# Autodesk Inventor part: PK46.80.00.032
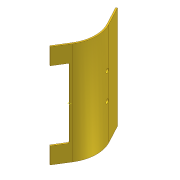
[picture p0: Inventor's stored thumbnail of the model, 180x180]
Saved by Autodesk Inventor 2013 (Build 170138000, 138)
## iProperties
Shininess: 64.0
Length Units: 11269
Angle Units: 11279
Time Units: 11290
Mass Units: 11283
Length Display Precision: 3
Angle Display Precision: 2
Compacted: True
Part Number: PK46.80.00.032
Document SubType Name: Sheet Metal
Created: 2005-01
Material: Steel, Mild
Designer: SAlex
Manufacturer: Standard
Standards Organization: Custom
Density: 7.86 g/cm^3
Flat Pattern Width: 136.565 cm
Flat Pattern Length: 151.087 cm
Flat Pattern Area: 20633.1 cm^2
Sheet Metal Rule: Default
Mass: 119662 g
Surface Area: 19816.5 cm^2
Volume: 15224.2 cm^3
Density: 0.0
Volumn: 0.0
Area: 0.0
PropertySet Name: Model Information
Control State: 0
Master: False
Checked Out: False
Checked Out Date: 2008-10-15
Last Check In Date: 2008-10-15
Author: SAlex
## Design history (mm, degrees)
node "Contour Flange1"
  sketch "Sketch1"
    geometry: L1 (0, 0)-(105.376, 169.988); L2 (118.157, 577.787)-(0, 798.103); A1 r 408 centre (-241.398, 384.956) between (105.376, 169.988) and (118.157, 577.787)
    constraints: 4 end point, 2 point on circle, 2 tangent, 1 centre point, 1 other
    dimensions: "d1" = 60 deg dimension on A1.centre L2.start L1.end; "d2" = 200 distance of L1.start L1.end; "d3" = 408 radius of A1; "d4" = 250 distance of L2.start L2.end; "d5" = 0 horizontal distance of L2.end L1.start
sketch "Sketch2"
  geometry: L1 (1240, -200)-(1240, 0) reference; L2 (0, -200)-(0, 0) reference; L3 (0, -200)-(1240, -200) reference; L4 (200, -200)-(1040, -200); L5 (1040, -200)-(1040, -30); L6 (1040, -30)-(200, -30); L7 (200, -30)-(200, -200)
  constraints: 8 end point, 2 parallel, 1 horizontal, 1 perpendicular, 1 point on line
  dimensions: "d13" = 200 distance between parallel lines of L7 L2; "d14" = 200 distance between parallel lines of L1 L5 (= d13); "d15" = 170 distance between parallel lines of L3 L6
extrude "Extrusion1" cut sketch "Sketch2" stored distance "d16" = 10; taper "d17" = 0 deg
fillet "Fillet1" dims "d18" = 10
workplane "Work Plane1"
sketch "Sketch4"
  geometry: L1 (0, 250)-(0, 0) reference; L2 (1240, 250)-(0, 250) reference; C1 r 25 at (460, -45); C2 r 25 at (780, -45)
  constraints: 2 centre point, 1 equal radius
  dimensions: "d24" = 0 vertical distance of C2.centre C1.centre; "d25" = 295 distance from line of C1.centre L2; "d26" = 50 diameter of C1; "d27" = 320 distance of C2.centre C1.centre; "d28" = 460 distance from line of C1.centre L1
extrude "Extrusion3" cut sketch "Sketch4" stored distance "d29" = 10; taper "d30" = 0 deg
body "Solid1"
face "Plate1" dims "d6" = 1240, "d7" = 16 (= BendReliefWidth), "d9" = 32 (= MinimumRemnant), "d11" = 16 (= BendRadius), "d12" = 0.5, "Thickness" = 16
bend "Bend1" dims "d7" = 16 (= BendReliefWidth), "d8" = 8 (= BendReliefDepth), "d9" = 32 (= MinimumRemnant), "d10" = 16 (= BendRadius), "d11" = 16 (= BendRadius), "d12" = 0.5, "SeamGap" = 0.01, "Thickness" = 16
node "FlatPattern"
feature "FlatPatternExtrusion2" dims "d0" = 16 (derived)
other parameters: "BendRadius" = 16 (= Thickness), "BendReliefWidth" = 16 (= Thickness), "BendReliefDepth" = 8 (= 0.5 x Thickness), "CornerReliefSize" = 64 (= 4 x Thickness), "MinimumRemnant" = 32 (= 2 x Thickness), "TransitionRadius" = 16 (= BendRadius), "JacobiRadiusSize" = 16 (= Thickness), "GapSize" = 16 (= Thickness)
